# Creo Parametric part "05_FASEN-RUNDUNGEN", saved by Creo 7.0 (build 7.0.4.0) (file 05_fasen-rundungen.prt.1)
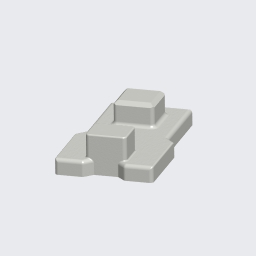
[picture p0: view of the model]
Units: millimeter Kilogram Sec (mmKs); MM, KILOGRAM, SECS
Materials in the file: S235JRG2

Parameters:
  PTC_MATERIAL_NAME = "S235JRG2"
  BENENNUNG = "XXX"
  DATUM = "XX.XX.XX"
  ERSTELLER = "ARINDA"
  TEILETYP = "Fertigungsteil"
  SELECT_EN_NAME = "S235JRG2"
  SELECT_DIN_NAME = "RSt37-2"
  SELECT_DIN_NUMBER = "1.0038"
  SELECT_ASTM_NAME = "A 283 M Grade 2"
  MATERIAL_GROUP = "ME_ST_Baustahl"
  STANDARD_EN_DELIVERYSPEC = "DIN EN 10025"
  STANDARD_DIN_DELIVERYSPEC = "DIN 17100"

Other parameters: MASSE

Created from: ARINDA-STARTTEIL.PRT

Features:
  1. coordinate system "CS0"
  2. datum plane "DTM1", "T_RECHTS_Y-Z"
  3. datum plane "DTM2", "T_OBEN_X-Z"
  4. datum plane "DTM3", "T_VORNE_X-Y"
  5. datum axis "T_X-ACHSE"
  6. datum axis "A_1"
  7. datum axis "A_2"
  8. imported feature "Import-ke ID 40"

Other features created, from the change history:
  feature "Schräge 1"
  feature "Schräge 2"

Other named items: T_BASIC, T_Y-ACHSE, T_Z-ACHSE

Layers: 00_STD-ACHSEN, 00_STD-EBENEN, 00_STD-KOORDSYS, SAMMELFLÄCHEN, VOLUMENGEOMETRIE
